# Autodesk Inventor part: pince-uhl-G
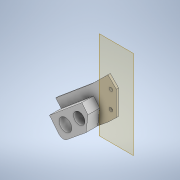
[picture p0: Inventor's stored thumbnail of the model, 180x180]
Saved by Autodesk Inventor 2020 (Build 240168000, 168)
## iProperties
Created: 2022-02
Part Number: pince-uhl-G
Material: Générique
Document SubType Name: Modeling
Designer: bruno
Density: 1 g/cm^3
Appearance: Par défaut
Author: bruno
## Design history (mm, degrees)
node "Plan de construction1"
sketch "Esquisse1"
  geometry: L1 (-5.15, 32.999)-(-17.137, 23.172); L2 (-17.137, 23.172)-(-70.014, -20.174); L3 (-0.176, -17.069)-(-0.176, 3.969) reference; L4 (-6.227, -22.088)-(0.143, -15.835) reference; L5 (-6.674, -23.391)-(-0.176, -17.069) reference; L6 (-9.751, 8.635)-(-13.148, 5.27) reference; L7 (-0.176, 3.969)-(-7.25, 11.111); L8 (-7.25, 11.111)-(-20.832, -2.341); L9 (-20.832, -2.341)-(-16.006, -8.227); L10 (-16.006, -8.227)-(-43.363, -30.653); L11 (-44.06, -37.69)-(-39.214, -43.601); L12 (-6.674, -23.391)-(-32.178, -44.298); L13 (-36.045, -47.468)-(-37.599, -45.572); L14 (-20.832, -2.341)-(-51.797, -28.252); L15 (-51.797, -28.252)-(-44.642, -36.802); C1 r 2.8 at (-17.137, 23.172) reference; C2 r 1.75 at (-5.15, 32.999) reference; C3 r 1.5 at (-4.674, 1.655) reference; C4 r 1.5 at (-4.68, -13.34) reference; C5 r 5.446 at (-33.564, -34.027); C6 r 4.861 at (-21.786, -23.391); A1 r 5 centre (-40.194, -34.52) between (-43.363, -30.653) and (-44.06, -37.69); A2 r 5 centre (-35.348, -40.431) between (-39.214, -43.601) and (-32.178, -44.298); 3 further points
  constraints: 22 end point, 5 point on circle, 4 centre point, 4 perpendicular, 4 point on line, 4 tangent, 2 parallel, 1 collinear, 1 equal radius
  dimensions: "d1" = 25 distance between parallel lines of L2 L10; "d2" = 5 radius of A1
extrude "Extrusion3" new body sketch "Esquisse1" distance "d10" = 2; taper "d11" = 0 deg
sketch "Esquisse6"
  geometry: L1 (20.832, -2.341)-(7.25, 11.111) reference; L2 (7.25, 11.111)-(0.176, 3.969) reference; L3 (0.176, 3.969)-(0.176, -17.069) reference; L4 (0.176, -17.069)-(6.674, -23.391) reference; L5 (6.674, -23.391)-(32.178, -44.298) reference; L6 (39.214, -43.601)-(44.06, -37.69) reference; L7 (44.642, -36.802)-(51.797, -28.252) reference; L8 (51.797, -28.252)-(20.832, -2.341) reference; L9 (51.797, -28.252)-(44.642, -36.802) reference; L10 (19.578, -10.679)-(14.34, -17.069); L11 (19.578, -10.679)-(47.176, -33.774); L12 (44.642, -36.802)-(51.797, -28.252) reference; L13 (14.34, -17.069)-(16.029, -31.06); C1 r 1.5 at (4.674, 1.655) reference; C2 r 1.5 at (4.68, -13.34) reference; C3 r 5.446 at (33.564, -34.027) reference; C4 r 4.861 at (21.786, -23.391) reference; A1 r 5 centre (35.348, -40.431) between (32.178, -44.298) and (39.214, -43.601) reference; A2 r 5 centre (40.194, -34.52) between (44.06, -37.69) and (44.642, -36.802) reference; 3 further points
  constraints: 6 end point, 2 perpendicular, 2 point on line
  dimensions: "d20" = 7.2 distance between parallel lines of L8 L11
extrude "Extrusion7" join sketch "Esquisse6" distance "d23" = 12; taper "d24" = 0 deg
node "Solide2"
node "Référence1"
node "Référence2"
node "Référence3"
node "Référence4"
node "Référence5"
node "Référence6"
node "Référence7"
node "Référence8"
node "Boucle projetée1"
